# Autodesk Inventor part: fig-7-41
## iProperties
Shininess: 77.0
Length Units: 11269
Angle Units: 11279
Time Units: 11290
Mass Units: 11283
Length Display Precision: 3
Angle Display Precision: 2
Created: 2002-01
Part Number: fig-7-41
Document SubType Name: Modeling
Designer: ***
Density: 0.0
Volumn: 0.0
Area: 0.0
PropertySet Name: Model Information
Control State: 0
Master: False
Checked Out: False
Author: ***
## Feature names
1. Extrusion1
2. Fillet1
3. Extrusion2
4. Extrusion3
5. Chamfer1
